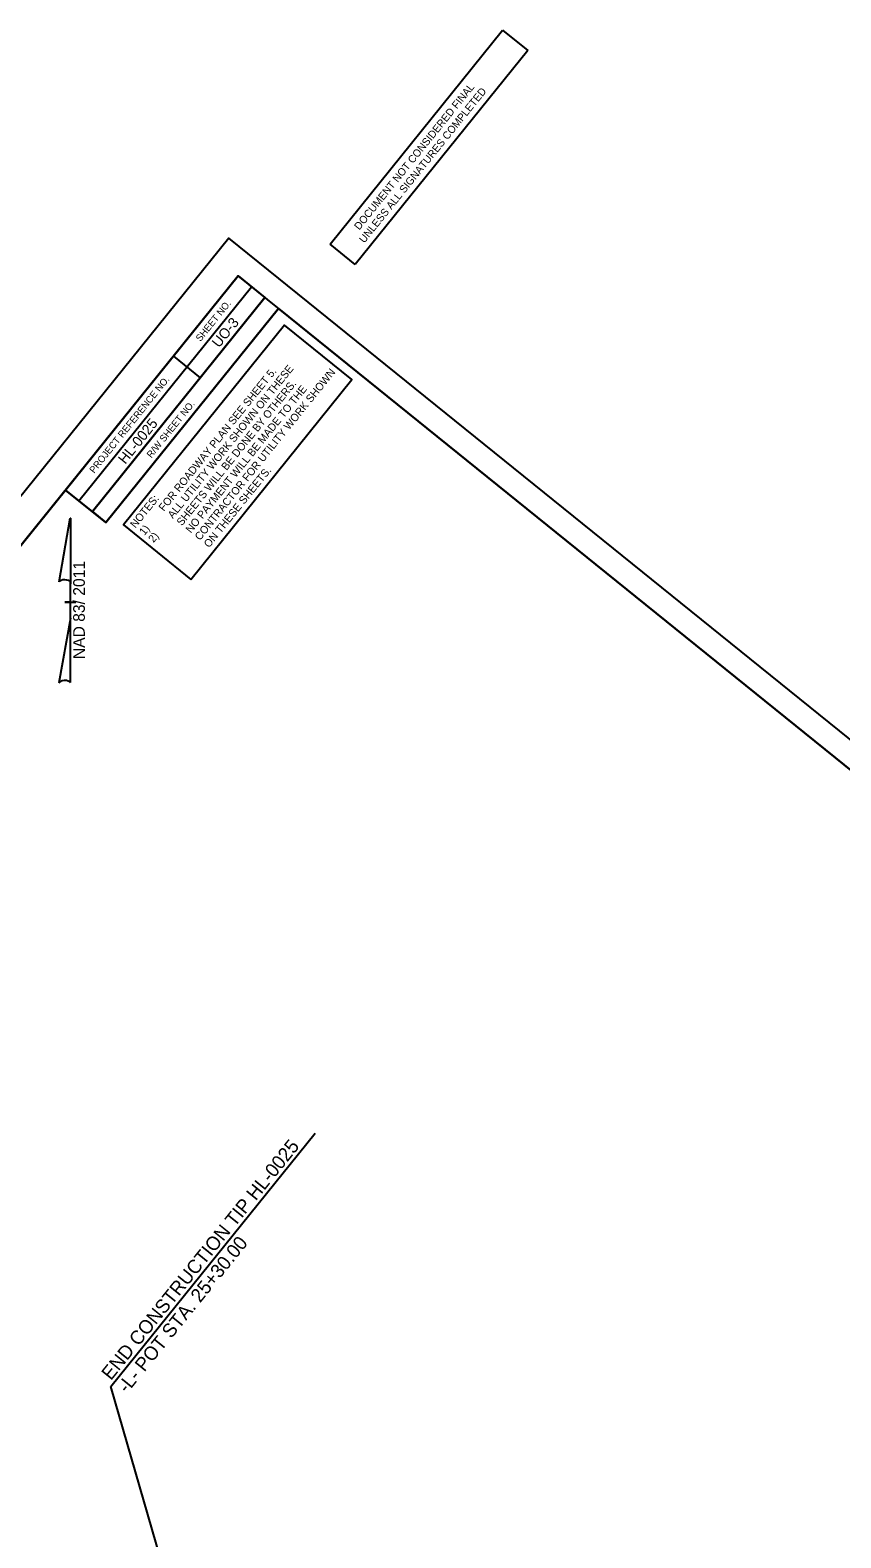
# Model space of a CAD drawing. Extents: x 1487875 to 1489967, y 498345 to 500495.
# Drawn here: x 1488787 to 1489377, y 499398 to 500495 of the extents above; entities that cross this region are included whole.
import ezdxf

# ---------------------------------------------------------------- set-up
doc = ezdxf.new("R2010")
doc.units = 0
for name, color, linetype in [('Cell Prop Down Guy _B', 7, 'Continuous'), ('Exist Conduit _B', 7, 'Continuous'), ('Exist Utilities Gas UG Line SUE LOS B', 7, 'Continuous'), ('Exist Utilities Sanitary Sewer Manhole CELL', 7, 'Continuous'), ('Exist Utilities TV UG Cable SUE LOS C', 7, 'Continuous'), ('Exist Utilities Water Fire Hydrant CELL', 7, 'Continuous'), ('Exist Utilities Water Meter CELL', 7, 'Continuous'), ('Prop Conduit _B', 7, 'Continuous'), ('Prop Guy Wire', 7, 'Continuous'), ('Prop UG Pow Cables', 7, 'Continuous')]:
    doc.layers.add(name, color=color, linetype=linetype)

msp = doc.modelspace()

# ---------------------------------------------------------------- linework, layer by layer
at = {"layer": 'Cell Prop Down Guy _B'}
for p, q in [((1488808.5, 500093.3), (1488816.7, 500139.6)), ((1488816.8, 500139.6), (1488816.7, 500139.6)), ((1488816.8, 500139.6), (1488816.7, 500139.6)), ((1488816.8, 500139.6), (1488816.8, 500091.8)), ((1488816.8, 500067), (1488816.8, 500093.2)), ((1488816.8, 500091.8), (1488816.8, 500093.2)), ((1488812.8, 500078.6), (1488812.7, 500078.6)), ((1488812.8, 500078.6), (1488820.8, 500078.6)), ((1488816.3, 500078.6), (1488812.8, 500078.6)), ((1488816.8, 500067), (1488808.4, 500019.8)), ((1488816.8, 500020), (1488816.8, 500067))]:
    msp.add_line(p, q, dxfattribs=at)
for centre, start_param, end_param in [((1488812.7, 500092.8), 0.216388, 2.908219), ((1488812.7, 500019.6), 0.201328, 3.141593)]:
    msp.add_ellipse(centre, major_axis=(4.23, -0.03), ratio=0.461098, start_param=start_param, end_param=end_param, dxfattribs=at)
at = {"layer": 'Exist Conduit _B'}
msp.add_line((1488832.8, 500144.4), (1488842.5, 500136.5), dxfattribs=at)
at = {"layer": 'Exist Utilities Sanitary Sewer Manhole CELL'}
for p, q in [((1488846.3, 499507.9), (1488995, 499692.2)), ((1488900.6, 499320), (1488846.3, 499507.9))]:
    msp.add_line(p, q, dxfattribs=at)
at = {"layer": 'Exist Utilities TV UG Cable SUE LOS C'}
for p, q in [((1488823, 500152.2), (1488948.6, 500307.9)), ((1488832.8, 500144.4), (1488958.3, 500300.1)), ((1488832.8, 500144.4), (1488958.3, 500300.1)), ((1488842.5, 500136.5), (1488968.1, 500292.2)), ((1488891.8, 500257.4), (1488911.3, 500241.7)), ((1488832.8, 500144.4), (1488842.5, 500136.5))]:
    msp.add_line(p, q, dxfattribs=at)
for points in [[(1488938.9, 500315.8), (1487997.2, 499148.2), (1488814.5, 498489), (1489756.2, 499656.7)], [(1488813.3, 500160.1), (1488938.9, 500315.8), (1488958.3, 500300.1), (1488832.8, 500144.4)], [(1488814.5, 498489), (1487997.2, 499148.1), (1488813.3, 500160.1), (1488842.5, 500136.5), (1488968.1, 500292.2), (1489756.2, 499656.7)]]:
    msp.add_lwpolyline(points, close=True, dxfattribs=at)
at = {"layer": 'Exist Utilities Water Fire Hydrant CELL'}
msp.add_lwpolyline([(1488842.5, 500136.5), (1488813.3, 500160.1), (1488087.8, 499260.5), (1488879.1, 498569.1), (1489756.2, 499656.7), (1488968.1, 500292.2)], close=True, dxfattribs=at)
msp.add_lwpolyline([(1488842.5, 500136.5), (1488813.3, 500160.1), (1488087.8, 499260.5), (1488879.1, 498569.1), (1489756.2, 499656.7), (1488968.1, 500292.2)], close=True, dxfattribs=at)
at = {"layer": 'Exist Utilities Water Meter CELL'}
msp.add_lwpolyline([(1488904.5, 500095.1), (1489021.6, 500240.5), (1488972.6, 500280), (1488855.4, 500134.7)], close=True, dxfattribs=at)
at = {"layer": 'Prop Guy Wire'}
for p, q in [((1489005.7, 500338.9), (1489131.3, 500494.6)), ((1489131.3, 500494.6), (1489149.6, 500479.8)), ((1489149.5, 500479.9), (1489024, 500324.1)), ((1489024, 500324.1), (1489005.7, 500338.9))]:
    msp.add_line(p, q, dxfattribs=at)
at = {"layer": 'Prop UG Pow Cables'}
msp.add_lwpolyline([(1488727.6, 498345.3), (1489784.4, 499655.8), (1488932, 500343.2), (1487875.2, 499032.7)], close=True, dxfattribs=at)

# ---------------------------------------------------------------- texts
at = {"layer": 'Cell Prop Down Guy _B'}
msp.add_text('NAD 83/ 2011', height=8.5, rotation=90, dxfattribs=at).set_placement((1488827.3, 500037.1))
at = {"layer": 'Exist Utilities Gas UG Line SUE LOS B'}
for s, height, p in [('FOR ROADWAY PLAN SEE SHEET 5.', 5.625, (1488884.8, 500144.2)), ('ALL UTILITY WORK SHOWN ON THESE', 5.625, (1488891.4, 500138.9)), ('CONTRACTOR FOR UTILITY WORK SHOWN', 5.625, (1488911.1, 500123)), ('SHEETS WILL BE DONE BY OTHERS.', 5.625, (1488897.9, 500133.6)), ('NO PAYMENT WILL BE MADE TO THE', 5.625, (1488904.5, 500128.3)), ('ON THESE SHEETS.', 5.625, (1488917.7, 500117.7)), ('NOTES:', 5.62, (1488864.1, 500132)), ('1)', 5.62, (1488870.7, 500126.7)), ('2)', 5.62, (1488877.3, 500121.4))]:
    msp.add_text(s, height=height, rotation=51.1228, dxfattribs=at).set_placement(p)
at = {"layer": 'Exist Utilities Sanitary Sewer Manhole CELL'}
for s, p in [('END CONSTRUCTION TIP HL-0025', (1488846.3, 499511.9)), ('-L- POT STA. 25+30.00', (1488858, 499502.5))]:
    msp.add_text(s, height=10, rotation=51.1156, dxfattribs=at).set_placement(p)
at = {"layer": 'Exist Utilities TV UG Cable SUE LOS C'}
for s, p in [('SHEET NO.', (1488911.4, 500267.7)), ('PROJECT REFERENCE NO.', (1488834, 500171.9)), ('R/W SHEET NO.', (1488875.7, 500183))]:
    msp.add_text(s, height=5, rotation=51.1157, dxfattribs=at).set_placement(p)
at = {"layer": 'Prop Conduit _B'}
for s, p in [('UO-3', (1488924.9, 500263.1)), ('HL-0025', (1488856.7, 500178.4))]:
    msp.add_text(s, height=7.5, rotation=51.1157, dxfattribs=at).set_placement(p)
at = {"layer": 'Prop Guy Wire'}
for s, p in [('DOCUMENT NOT CONSIDERED FINAL', (1489027, 500348.8)), ('UNLESS ALL SIGNATURES COMPLETED', (1489030.6, 500339.3))]:
    msp.add_text(s, height=5.5, rotation=51.1156, dxfattribs=at).set_placement(p)

doc.saveas('drawing.dxf')
